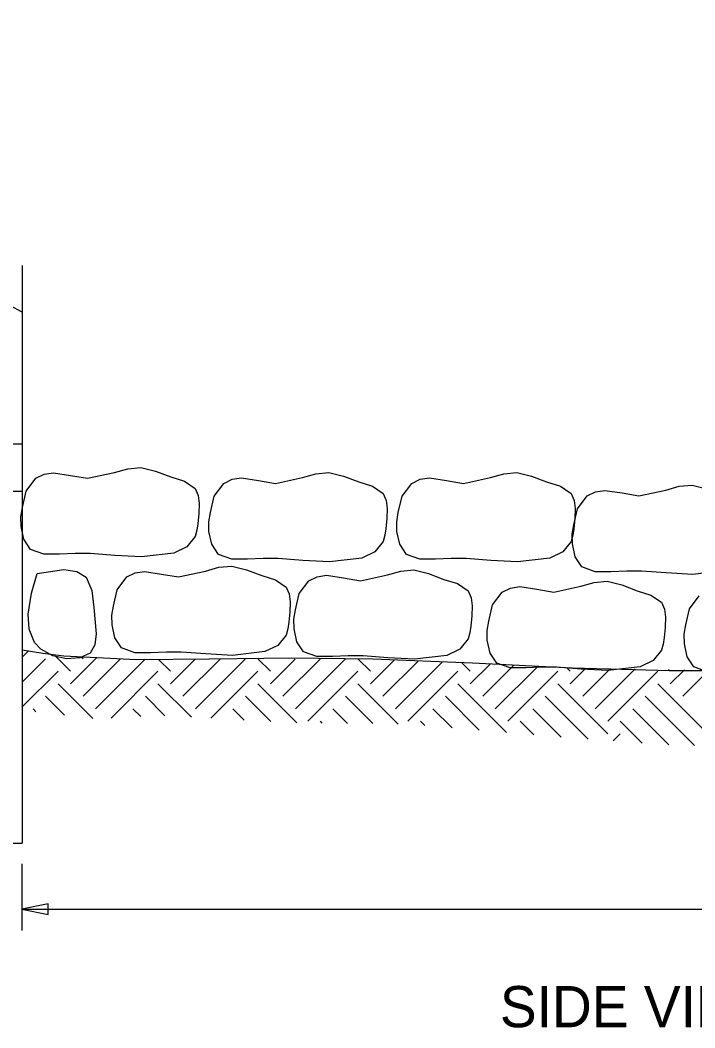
# Model space of a CAD drawing. Extents: x -439.1 to -407.9, y -458.1 to -436.2.
# Drawn here: x -431.879 to -428.606, y -444.35 to -439.459 of the extents above; entities that cross this region are included whole.
import ezdxf

# ---------------------------------------------------------------- set-up
doc = ezdxf.new("R2010")
doc.units = 0
doc.layers.add('Level 4', color=7, linetype='Continuous')

msp = doc.modelspace()

# ---------------------------------------------------------------- linework, layer by layer
at = {"layer": 'Level 4'}
for p, q in [((-431.8693, -440.8759), (-434.5358, -439.4587)), ((-431.8693, -440.6496), (-431.8693, -443.4544)), ((-438.1966, -441.516), (-431.8693, -441.516)), ((-438.1966, -441.7446), (-431.8693, -441.7446)), ((-431.8694, -442.5517), (-431.8391, -442.5215)), ((-431.6344, -442.6197), (-431.7077, -442.5464)), ((-431.5737, -442.5591), (-431.5824, -442.5504)), ((-431.8696, -442.6731), (-431.7556, -442.5591)), ((-431.6344, -442.6804), (-431.5083, -442.5543)), ((-431.5737, -442.741), (-431.3931, -442.5603)), ((-431.5131, -442.8016), (-431.2755, -442.564)), ((-431.1494, -442.6197), (-431.206, -442.5632)), ((-431.1494, -442.6804), (-431.0303, -442.5612)), ((-431.0888, -442.741), (-430.9083, -442.5604)), ((-431.0282, -442.8016), (-430.7871, -442.5604)), ((-430.6645, -442.6197), (-430.7238, -442.5604)), ((-430.6645, -442.6804), (-430.5446, -442.5604)), ((-430.6039, -442.741), (-430.4234, -442.5604)), ((-430.5433, -442.8016), (-430.3021, -442.5604)), ((-430.1796, -442.6197), (-430.2389, -442.5604)), ((-430.1796, -442.6804), (-430.063, -442.5638)), ((-430.119, -442.741), (-429.9461, -442.5681)), ((-430.0584, -442.8016), (-429.8299, -442.5731)), ((-429.6947, -442.6197), (-429.7369, -442.5775)), ((-429.6947, -442.6804), (-429.5988, -442.5844)), ((-429.6341, -442.741), (-429.4834, -442.5903)), ((-429.5735, -442.8016), (-429.3679, -442.5961)), ((-431.8697, -442.7945), (-431.695, -442.6197)), ((-431.4374, -442.8471), (-431.2101, -442.6197)), ((-430.9532, -442.8478), (-430.7251, -442.6197)), ((-430.4827, -442.8622), (-430.2402, -442.6197)), ((-429.9978, -442.8622), (-429.7553, -442.6197)), ((-429.5129, -442.8622), (-429.2704, -442.6197)), ((-429.2098, -442.6197), (-429.227, -442.6025)), ((-429.2098, -442.6804), (-429.1341, -442.6047)), ((-429.1492, -442.741), (-429.0147, -442.6065)), ((-429.0886, -442.8016), (-428.8953, -442.6083)), ((-429.0279, -442.8622), (-428.7855, -442.6197)), ((-428.7249, -442.6197), (-428.7338, -442.6108)), ((-428.7249, -442.6804), (-428.6565, -442.612)), ((-428.6643, -442.741), (-428.5371, -442.6138)), ((-431.5265, -442.8488), (-431.695, -442.6804)), ((-431.0479, -442.8425), (-431.2101, -442.6804)), ((-430.5364, -442.8691), (-430.7251, -442.6804)), ((-430.0445, -442.8761), (-430.2402, -442.6804)), ((-429.5186, -442.9171), (-429.7553, -442.6804)), ((-429.0279, -442.9228), (-429.2704, -442.6804)), ((-428.543, -442.9228), (-428.7855, -442.6804)), ((-431.6633, -442.8333), (-431.7556, -442.741)), ((-431.1762, -442.8354), (-431.2707, -442.741)), ((-430.6629, -442.8638), (-430.7858, -442.741)), ((-430.1682, -442.8736), (-430.3008, -442.741)), ((-429.6511, -442.9058), (-429.8159, -442.741)), ((-429.1234, -442.9486), (-429.331, -442.741)), ((-428.6075, -442.9796), (-428.8461, -442.741)), ((-431.8018, -442.8159), (-431.8162, -442.8016)), ((-431.2938, -442.839), (-431.3313, -442.8016)), ((-430.7912, -442.8568), (-430.8464, -442.8016)), ((-430.2906, -442.8725), (-430.3615, -442.8016)), ((-429.7836, -442.8945), (-429.8765, -442.8016)), ((-429.2542, -442.939), (-429.3916, -442.8016)), ((-428.731, -442.9773), (-428.9067, -442.8016)), ((-430.4129, -442.8714), (-430.4221, -442.8622)), ((-429.9161, -442.8832), (-429.9372, -442.8622)), ((-429.3861, -442.9283), (-429.4522, -442.8622)), ((-428.8618, -442.9677), (-428.9673, -442.8622)), ((-429.002, -442.9575), (-428.9673, -442.9228)), ((-432.0978, -443.4544), (-431.8693, -443.4544)), ((-431.8697, -443.555), (-431.8697, -443.8773)), ((-431.8697, -443.7744), (-420.5223, -443.7744))]:
    msp.add_line(p, q, dxfattribs=at)
for points in [[(-431.8679, -441.8241), (-431.8495, -441.7455), (-431.8022, -441.6828), (-431.7618, -441.6633), (-431.7168, -441.6566), (-431.634, -441.6689), (-431.5525, -441.6828), (-431.4212, -441.6549), (-431.3562, -441.6361), (-431.2929, -441.6303), (-431.2223, -441.6483), (-431.1483, -441.6763), (-431.0812, -441.6971), (-431.03, -441.7321), (-431.0156, -441.7657), (-431.0103, -441.8044), (-431.0113, -441.854), (-431.0169, -441.903), (-431.0216, -441.9352), (-431.03, -441.9654), (-431.0699, -442.0153), (-431.1334, -442.0454), (-431.2896, -442.064), (-431.4196, -442.0568), (-431.5393, -442.0476), (-431.611, -442.0477), (-431.6872, -442.0509), (-431.7643, -442.0509), (-431.8285, -442.0278), (-431.8607, -441.9789), (-431.8745, -441.9161), (-431.8753, -441.8692), (-431.8679, -441.8241)], [(-430.9559, -441.8485), (-430.9376, -441.7698), (-430.8902, -441.7072), (-430.8498, -441.6876), (-430.8048, -441.6809), (-430.722, -441.6932), (-430.6405, -441.7072), (-430.5092, -441.6793), (-430.4442, -441.6604), (-430.3809, -441.6546), (-430.3103, -441.6726), (-430.2363, -441.7006), (-430.1692, -441.7215), (-430.118, -441.7564), (-430.1036, -441.7901), (-430.0983, -441.8287), (-430.0993, -441.8784), (-430.1049, -441.9273), (-430.1097, -441.9595), (-430.118, -441.9898), (-430.158, -442.0396), (-430.2214, -442.0697), (-430.3776, -442.0883), (-430.5076, -442.0811), (-430.6273, -442.0719), (-430.6991, -442.072), (-430.7752, -442.0752), (-430.8523, -442.0752), (-430.9165, -442.0522), (-430.9487, -442.0032), (-430.9625, -441.9405), (-430.9633, -441.8936), (-430.9559, -441.8485)], [(-430.044, -441.8485), (-430.0256, -441.7698), (-429.9782, -441.7072), (-429.9379, -441.6876), (-429.8928, -441.6809), (-429.81, -441.6932), (-429.7285, -441.7072), (-429.5972, -441.6793), (-429.5322, -441.6604), (-429.4689, -441.6546), (-429.3984, -441.6726), (-429.3244, -441.7006), (-429.2572, -441.7215), (-429.2061, -441.7564), (-429.1917, -441.7901), (-429.1864, -441.8287), (-429.1874, -441.8784), (-429.1929, -441.9273), (-429.1977, -441.9595), (-429.2061, -441.9898), (-429.246, -442.0396), (-429.3095, -442.0697), (-429.4657, -442.0883), (-429.5956, -442.0811), (-429.7154, -442.0719), (-429.7871, -442.072), (-429.8632, -442.0752), (-429.9403, -442.0752), (-430.0045, -442.0522), (-430.0368, -442.0032), (-430.0505, -441.9405), (-430.0513, -441.8936), (-430.044, -441.8485)], [(-431.4262, -442.3027), (-431.4078, -442.2241), (-431.3605, -442.1614), (-431.3201, -442.1419), (-431.275, -442.1351), (-431.1922, -442.1475), (-431.1107, -442.1614), (-430.9794, -442.1335), (-430.9144, -442.1147), (-430.8512, -442.1089), (-430.7806, -442.1269), (-430.7066, -442.1549), (-430.6395, -442.1757), (-430.5883, -442.2107), (-430.5739, -442.2443), (-430.5686, -442.283), (-430.5696, -442.3326), (-430.5751, -442.3816), (-430.5799, -442.4138), (-430.5883, -442.444), (-430.6282, -442.4939), (-430.6917, -442.524), (-430.8479, -442.5426), (-430.9778, -442.5354), (-431.0976, -442.5262), (-431.1693, -442.5263), (-431.2455, -442.5294), (-431.3226, -442.5294), (-431.3868, -442.5064), (-431.419, -442.4575), (-431.4328, -442.3947), (-431.4336, -442.3478), (-431.4262, -442.3027)], [(-431.7967, -442.1451), (-431.666, -442.1259), (-431.6039, -442.1356), (-431.5576, -442.1634), (-431.5304, -442.227), (-431.5208, -442.3106), (-431.5096, -442.4372), (-431.5158, -442.4909), (-431.5392, -442.5312), (-431.5883, -442.555), (-431.653, -442.5587), (-431.7205, -442.544), (-431.7783, -442.5128), (-431.8092, -442.479), (-431.8345, -442.4157), (-431.8395, -442.3428), (-431.8243, -442.2404), (-431.7967, -442.1451)], [(-430.5435, -442.3211), (-430.5252, -442.2425), (-430.4778, -442.1798), (-430.4374, -442.1603), (-430.3924, -442.1535), (-430.3096, -442.1659), (-430.2281, -442.1798), (-430.0968, -442.1519), (-430.0318, -442.1331), (-429.9685, -442.1272), (-429.8979, -442.1453), (-429.8239, -442.1733), (-429.7568, -442.1941), (-429.7056, -442.2291), (-429.6912, -442.2627), (-429.6859, -442.3014), (-429.6869, -442.351), (-429.6925, -442.4), (-429.6973, -442.4322), (-429.7056, -442.4624), (-429.7456, -442.5123), (-429.809, -442.5424), (-429.9652, -442.561), (-430.0952, -442.5537), (-430.2149, -442.5445), (-430.2866, -442.5446), (-430.3628, -442.5478), (-430.4399, -442.5478), (-430.5041, -442.5248), (-430.5363, -442.4759), (-430.5501, -442.4131), (-430.5509, -442.3662), (-430.5435, -442.3211)], [(-429.6057, -442.3763), (-429.5873, -442.2977), (-429.54, -442.235), (-429.4996, -442.2154), (-429.4545, -442.2087), (-429.3717, -442.221), (-429.2903, -442.235), (-429.1589, -442.2071), (-429.094, -442.1883), (-429.0307, -442.1824), (-428.9601, -442.2004), (-428.8861, -442.2284), (-428.819, -442.2493), (-428.7678, -442.2843), (-428.7534, -442.3179), (-428.7481, -442.3566), (-428.7491, -442.4062), (-428.7547, -442.4551), (-428.7594, -442.4874), (-428.7678, -442.5176), (-428.8077, -442.5675), (-428.8712, -442.5975), (-429.0274, -442.6161), (-429.1574, -442.6089), (-429.2771, -442.5997), (-429.3488, -442.5998), (-429.425, -442.603), (-429.5021, -442.603), (-429.5663, -442.58), (-429.5985, -442.531), (-429.6123, -442.4683), (-429.6131, -442.4214), (-429.6057, -442.3763)], [(-431.7433, -443.7482), (-431.8697, -443.7744), (-431.7433, -443.8007)]]:
    msp.add_lwpolyline(points, close=True, dxfattribs=at)
for points in [[(-428.4583, -442.1305), (-428.6145, -442.1491), (-428.7445, -442.1419), (-428.8642, -442.1327), (-428.9359, -442.1328), (-429.0121, -442.136), (-429.0892, -442.136), (-429.1534, -442.113), (-429.1856, -442.064), (-429.1994, -442.0013), (-429.2002, -441.9543), (-429.1928, -441.9092), (-429.1928, -441.9092), (-429.1744, -441.8306), (-429.1271, -441.768), (-429.0867, -441.7484), (-429.0417, -441.7417), (-428.9589, -441.754), (-428.8774, -441.768), (-428.7461, -441.7401), (-428.6811, -441.7212), (-428.6178, -441.7154), (-428.5472, -441.7334)], [(-428.5459, -442.6214), (-428.61, -442.5984), (-428.6423, -442.5494), (-428.656, -442.4867), (-428.6568, -442.4398), (-428.6495, -442.3947), (-428.6495, -442.3947), (-428.6311, -442.316), (-428.5838, -442.2534)], [(-424.7422, -442.6326), (-425.1968, -442.622), (-425.6511, -442.6181), (-426.0334, -442.6269), (-426.4158, -442.6326), (-426.8775, -442.6191), (-427.3391, -442.6037), (-427.7935, -442.6077), (-428.2481, -442.6181), (-428.7243, -442.6177), (-429.2003, -442.6037), (-429.6837, -442.5801), (-430.1669, -442.5604), (-430.5634, -442.556), (-430.9604, -442.5604), (-431.3146, -442.5644), (-431.6674, -442.546), (-431.7686, -442.5331), (-431.8694, -442.5172)]]:
    msp.add_lwpolyline(points, dxfattribs=at)

# ---------------------------------------------------------------- texts
msp.add_text('SIDE VIEW', height=0.2, dxfattribs=at).set_placement((-429.5514, -444.3475))

doc.saveas('drawing.dxf')
